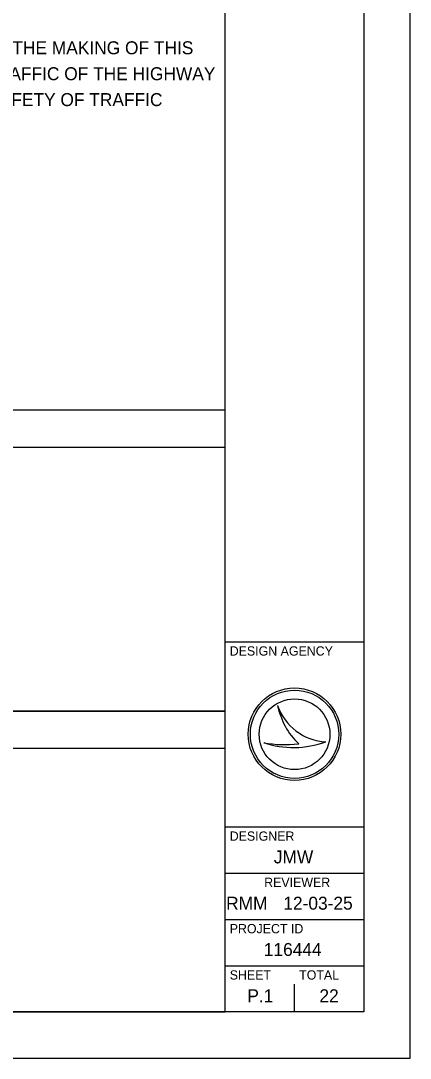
# Model space of a CAD drawing. Extents: x 0 to 29006, y 0 to 889393.
# Drawn here: x 29.79 to 34, y 0 to 11.21 of the extents above; entities that cross this region are included whole.
import ezdxf

# ---------------------------------------------------------------- set-up
doc = ezdxf.new("R2010")
doc.units = 0
for name, color, linetype in [('SH_Border', 7, 'Continuous'), ('SH_Cut_Line', 7, 'Continuous'), ('SH_Data', 7, 'Continuous')]:
    doc.layers.add(name, color=color, linetype=linetype)

msp = doc.modelspace()

# ---------------------------------------------------------------- linework, layer by layer
at = {"layer": 'SH_Border'}
for p, q in [((32, 0.5), (32, 21.5)), ((32, 4.5), (33.5, 4.5)), ((32, 2.5), (33.5, 2.5)), ((32, 2), (33.5, 2)), ((32, 1.5), (33.5, 1.5)), ((32, 1), (33.5, 1))]:
    msp.add_line(p, q, dxfattribs=at)
msp.add_lwpolyline([(1.5, 21.5), (33.5, 21.5), (33.5, 0.5), (1.5, 0.5)], close=True, dxfattribs=at)
at = {"layer": 'SH_Cut_Line'}
msp.add_lwpolyline([(0, 0), (34, 0), (34, 22), (0, 22)], close=True, dxfattribs=at)
at = {"layer": 'SH_Data'}
for p, q in [((29.2, 6.6), (32, 6.6)), ((32.567, 3.81), (32.567, 3.81)), ((32.75, 3.5), (32.75, 3.5)), ((32.417, 3.41), (32.417, 3.41)), ((33.087, 3.419), (33.087, 3.419)), ((29.2, 3.35), (32, 3.35)), ((32.75, 0.5), (32.75, 0.8)), ((32.375, 0.675), (32.375, 0.675))]:
    msp.add_line(p, q, dxfattribs=at)
for points in [[(32, 7), (29.2, 7), (29.2, 3.75), (32, 3.75)], [(32, 3.75), (29.2, 3.75), (29.2, 0.5), (32, 0.5)]]:
    msp.add_lwpolyline(points, close=True, dxfattribs=at)
for radius in [0.5, 0.477, 0.477, 0.382]:
    msp.add_circle((32.75, 3.5), radius, dxfattribs=at)
for centre, radius, start, end in [((33.116, 3.998), 0.58, 198.9257, 198.9319), ((33.347, 3.97), 0.796, 191.6379, 191.6421), ((33.116, 3.998), 0.58, 198.9319, 267.1657), ((33.347, 3.97), 0.796, 191.6421, 226.0947), ((32.739, 4.37), 1.013, 251.4576, 290.0832), ((32.648, 4.654), 1.266, 259.4964, 259.4995), ((32.739, 4.37), 1.013, 251.4527, 251.4576), ((32.648, 4.654), 1.266, 259.4995, 276.6672)]:
    msp.add_arc(centre, radius, start, end, dxfattribs=at)

# ---------------------------------------------------------------- texts
for s, height, p in [(' I HEREBY APPROVE THESE PLANS AND DECLARE THAT THE MAKING OF THIS', 0.14, (24.5, 10.846)), ('IMPROVEMENT WILL NOT REQUIRE THE CLOSING TO TRAFFIC OF THE HIGHWAY', 0.14, (24.5, 10.566)), ('AND THAT PROVISIONS FOR THE MAINTENANCE AND SAFETY OF TRAFFIC', 0.14, (24.5, 10.286)), ('DESIGN AGENCY', 0.1, (32.05, 4.35)), ('DESIGNER', 0.1, (32.05, 2.35)), ('JMW', 0.14, (32.526, 2.105)), ('REVIEWER', 0.1, (32.422, 1.85)), ('RMM', 0.14, (32.011, 1.605)), ('12-03-25', 0.14, (32.629, 1.605)), ('PROJECT ID', 0.1, (32.05, 1.35)), ('116444', 0.14, (32.418, 1.105)), ('SHEET', 0.1, (32.05, 0.85)), ('TOTAL', 0.1, (32.8, 0.85)), ('P.1', 0.14, (32.24, 0.605)), ('22', 0.14, (33.019, 0.605))]:
    msp.add_text(s, height=height, dxfattribs=at).set_placement(p)

doc.saveas('drawing.dxf')
